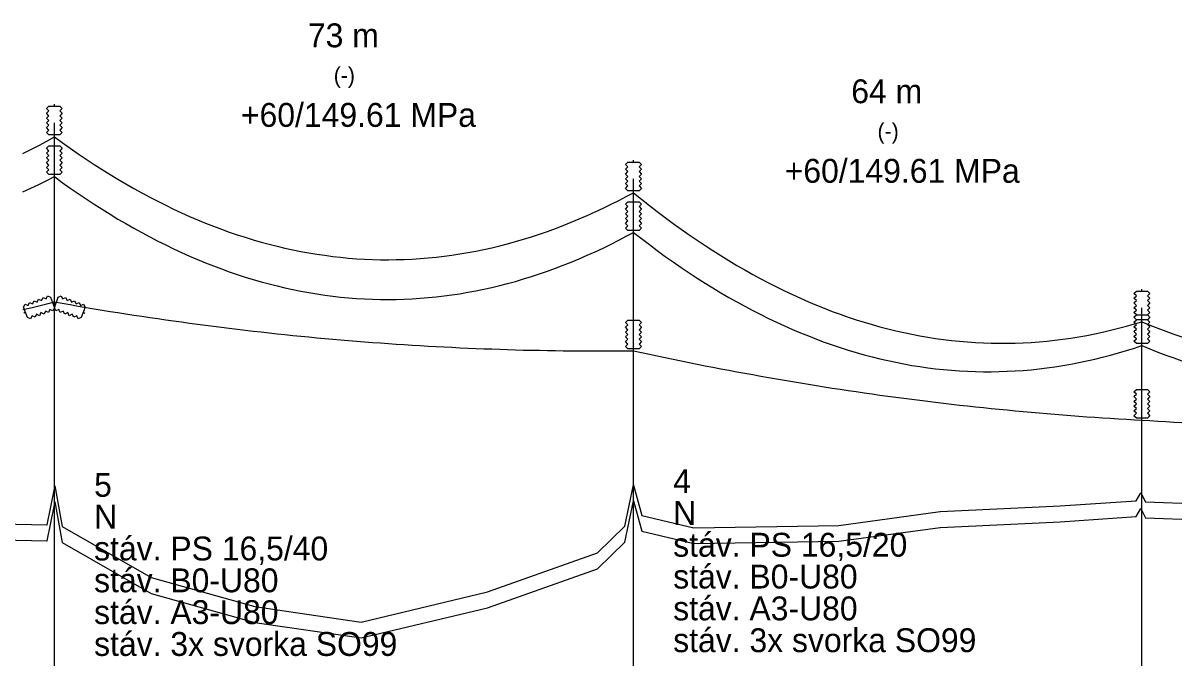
# Model space of a CAD drawing. Extents: x -21 to 625, y 813 to 990.
# Drawn here: x 314.9 to 459.7, y 910 to 989.8 of the extents above; entities that cross this region are included whole.
import ezdxf

# ---------------------------------------------------------------- set-up
doc = ezdxf.new("R2010")
doc.units = 0
for name, color, linetype in [('Vrstva 11', 7, 'Continuous'), ('Vrstva 12', 7, 'Continuous'), ('Vrstva 13', 7, 'Continuous'), ('Vrstva 14', 7, 'Continuous'), ('Vrstva 15', 7, 'Continuous'), ('Vrstva 29', 7, 'Continuous'), ('Vrstva 3', 7, 'Continuous')]:
    doc.layers.add(name, color=color, linetype=linetype)

msp = doc.modelspace()

# ---------------------------------------------------------------- linework, layer by layer
at = {"layer": 'Vrstva 11'}
for points in [[(314.9, 973.38), (315.9, 973.89), (316.9, 974.41), (317.9, 974.96), (318.86, 975.49)], [(318.86, 975.49), (319.86, 974.76), (320.86, 974.05), (321.86, 973.36), (322.86, 972.68), (323.86, 972.02), (324.86, 971.38), (325.86, 970.76), (326.86, 970.15), (327.86, 969.57), (328.86, 969), (329.86, 968.44), (330.86, 967.91), (331.86, 967.39), (332.86, 966.89), (333.86, 966.41), (334.86, 965.94), (335.86, 965.49), (336.86, 965.06), (337.86, 964.65), (338.86, 964.26), (339.86, 963.88), (340.86, 963.52), (341.86, 963.18), (342.86, 962.86), (343.86, 962.55), (344.86, 962.26), (345.86, 961.99), (346.86, 961.74), (347.86, 961.5), (348.86, 961.28), (349.86, 961.08), (350.86, 960.9), (351.86, 960.73), (352.86, 960.59), (353.86, 960.46), (354.86, 960.34), (355.86, 960.25), (356.86, 960.17), (357.86, 960.11), (358.86, 960.07), (359.86, 960.04), (360.86, 960.04), (361.86, 960.05), (362.86, 960.08), (363.86, 960.12), (364.86, 960.19), (365.86, 960.27), (366.86, 960.37), (367.86, 960.48), (368.86, 960.62), (369.86, 960.77), (370.86, 960.94), (371.86, 961.12), (372.86, 961.33), (373.86, 961.55), (374.86, 961.79), (375.86, 962.05), (376.86, 962.32), (377.86, 962.62), (378.86, 962.93), (379.86, 963.25), (380.86, 963.6), (381.86, 963.96), (382.86, 964.34), (383.86, 964.74), (384.86, 965.16), (385.86, 965.59), (386.86, 966.04), (387.86, 966.51), (388.86, 967), (389.86, 967.5), (390.86, 968.02), (391.68, 968.46)], [(314.9, 968.55), (315.9, 969.02), (316.9, 969.5), (317.9, 970), (318.86, 970.49)], [(314.9, 968.55), (315.9, 969.02), (316.9, 969.5), (317.9, 970), (318.86, 970.49)], [(318.86, 970.49), (319.86, 969.76), (320.86, 969.05), (321.86, 968.36), (322.86, 967.68), (323.86, 967.02), (324.86, 966.38), (325.86, 965.76), (326.86, 965.15), (327.86, 964.57), (328.86, 964), (329.86, 963.44), (330.86, 962.91), (331.86, 962.39), (332.86, 961.89), (333.86, 961.41), (334.86, 960.94), (335.86, 960.49), (336.86, 960.06), (337.86, 959.65), (338.86, 959.26), (339.86, 958.88), (340.86, 958.52), (341.86, 958.18), (342.86, 957.86), (343.86, 957.55), (344.86, 957.26), (345.86, 956.99), (346.86, 956.74), (347.86, 956.5), (348.86, 956.28), (349.86, 956.08), (350.86, 955.9), (351.86, 955.73), (352.86, 955.59), (353.86, 955.46), (354.86, 955.34), (355.86, 955.25), (356.86, 955.17), (357.86, 955.11), (358.86, 955.07), (359.86, 955.04), (360.86, 955.04), (361.86, 955.05), (362.86, 955.08), (363.86, 955.12), (364.86, 955.19), (365.86, 955.27), (366.86, 955.37), (367.86, 955.48), (368.86, 955.62), (369.86, 955.77), (370.86, 955.94), (371.86, 956.12), (372.86, 956.33), (373.86, 956.55), (374.86, 956.79), (375.86, 957.05), (376.86, 957.32), (377.86, 957.62), (378.86, 957.93), (379.86, 958.25), (380.86, 958.6), (381.86, 958.96), (382.86, 959.34), (383.86, 959.74), (384.86, 960.16), (385.86, 960.59), (386.86, 961.04), (387.86, 961.51), (388.86, 962), (389.86, 962.5), (390.86, 963.02), (391.68, 963.46)], [(318.86, 970.49), (319.86, 969.76), (320.86, 969.05), (321.86, 968.36), (322.86, 967.68), (323.86, 967.02), (324.86, 966.38), (325.86, 965.76), (326.86, 965.15), (327.86, 964.57), (328.86, 964), (329.86, 963.44), (330.86, 962.91), (331.86, 962.39), (332.86, 961.89), (333.86, 961.41), (334.86, 960.94), (335.86, 960.49), (336.86, 960.06), (337.86, 959.65), (338.86, 959.26), (339.86, 958.88), (340.86, 958.52), (341.86, 958.18), (342.86, 957.86), (343.86, 957.55), (344.86, 957.26), (345.86, 956.99), (346.86, 956.74), (347.86, 956.5), (348.86, 956.28), (349.86, 956.08), (350.86, 955.9), (351.86, 955.73), (352.86, 955.59), (353.86, 955.46), (354.86, 955.34), (355.86, 955.25), (356.86, 955.17), (357.86, 955.11), (358.86, 955.07), (359.86, 955.04), (360.86, 955.04), (361.86, 955.05), (362.86, 955.08), (363.86, 955.12), (364.86, 955.19), (365.86, 955.27), (366.86, 955.37), (367.86, 955.48), (368.86, 955.62), (369.86, 955.77), (370.86, 955.94), (371.86, 956.12), (372.86, 956.33), (373.86, 956.55), (374.86, 956.79), (375.86, 957.05), (376.86, 957.32), (377.86, 957.62), (378.86, 957.93), (379.86, 958.25), (380.86, 958.6), (381.86, 958.96), (382.86, 959.34), (383.86, 959.74), (384.86, 960.16), (385.86, 960.59), (386.86, 961.04), (387.86, 961.51), (388.86, 962), (389.86, 962.5), (390.86, 963.02), (391.68, 963.46)], [(391.68, 968.46), (392.68, 967.66), (393.68, 966.87), (394.68, 966.09), (395.68, 965.34), (396.68, 964.6), (397.68, 963.88), (398.68, 963.18), (399.68, 962.49), (400.68, 961.83), (401.68, 961.18), (402.68, 960.55), (403.68, 959.93), (404.68, 959.33), (405.68, 958.76), (406.68, 958.19), (407.68, 957.65), (408.68, 957.12), (409.68, 956.62), (410.68, 956.13), (411.68, 955.65), (412.68, 955.2), (413.68, 954.76), (414.68, 954.34), (415.68, 953.94), (416.68, 953.55), (417.68, 953.18), (418.68, 952.83), (419.68, 952.5), (420.68, 952.19), (421.68, 951.89), (422.68, 951.61), (423.68, 951.35), (424.68, 951.1), (425.68, 950.88), (426.68, 950.67), (427.68, 950.48), (428.68, 950.3), (429.68, 950.15), (430.68, 950.01), (431.68, 949.89), (432.68, 949.78), (433.68, 949.7), (434.68, 949.63), (435.68, 949.58), (436.68, 949.55), (437.68, 949.53), (438.68, 949.54), (439.68, 949.56), (440.68, 949.59), (441.68, 949.65), (442.68, 949.72), (443.68, 949.81), (444.68, 949.92), (445.68, 950.05), (446.68, 950.19), (447.68, 950.35), (448.68, 950.53), (449.68, 950.72), (450.68, 950.94), (451.68, 951.17), (452.68, 951.42), (453.68, 951.69), (454.68, 951.97), (455.62, 952.25)], [(391.68, 963.46), (392.68, 962.69), (393.68, 961.93), (394.68, 961.19), (395.68, 960.46), (396.68, 959.76), (397.68, 959.07), (398.68, 958.4), (399.68, 957.74), (400.68, 957.11), (401.68, 956.49), (402.68, 955.89), (403.68, 955.31), (404.68, 954.74), (405.68, 954.19), (406.68, 953.66), (407.68, 953.15), (408.68, 952.66), (409.68, 952.18), (410.68, 951.72), (411.68, 951.28), (412.68, 950.85), (413.68, 950.45), (414.68, 950.06), (415.68, 949.69), (416.68, 949.33), (417.68, 949), (418.68, 948.68), (419.68, 948.38), (420.68, 948.09), (421.68, 947.83), (422.68, 947.58), (423.68, 947.35), (424.68, 947.14), (425.68, 946.94), (426.68, 946.76), (427.68, 946.6), (428.68, 946.46), (429.68, 946.34), (430.68, 946.23), (431.68, 946.14), (432.68, 946.07), (433.68, 946.01), (434.68, 945.98), (435.68, 945.96), (436.68, 945.96), (437.68, 945.97), (438.68, 946.01), (439.68, 946.06), (440.68, 946.13), (441.68, 946.21), (442.68, 946.32), (443.68, 946.44), (444.68, 946.58), (445.68, 946.73), (446.68, 946.91), (447.68, 947.1), (448.68, 947.31), (449.68, 947.54), (450.68, 947.78), (451.68, 948.05), (452.68, 948.33), (453.68, 948.63), (454.68, 948.94), (455.62, 949.25)], [(391.68, 963.46), (392.68, 962.69), (393.68, 961.93), (394.68, 961.19), (395.68, 960.46), (396.68, 959.76), (397.68, 959.07), (398.68, 958.4), (399.68, 957.74), (400.68, 957.11), (401.68, 956.49), (402.68, 955.89), (403.68, 955.31), (404.68, 954.74), (405.68, 954.19), (406.68, 953.66), (407.68, 953.15), (408.68, 952.66), (409.68, 952.18), (410.68, 951.72), (411.68, 951.28), (412.68, 950.85), (413.68, 950.45), (414.68, 950.06), (415.68, 949.69), (416.68, 949.33), (417.68, 949), (418.68, 948.68), (419.68, 948.38), (420.68, 948.09), (421.68, 947.83), (422.68, 947.58), (423.68, 947.35), (424.68, 947.14), (425.68, 946.94), (426.68, 946.76), (427.68, 946.6), (428.68, 946.46), (429.68, 946.34), (430.68, 946.23), (431.68, 946.14), (432.68, 946.07), (433.68, 946.01), (434.68, 945.98), (435.68, 945.96), (436.68, 945.96), (437.68, 945.97), (438.68, 946.01), (439.68, 946.06), (440.68, 946.13), (441.68, 946.21), (442.68, 946.32), (443.68, 946.44), (444.68, 946.58), (445.68, 946.73), (446.68, 946.91), (447.68, 947.1), (448.68, 947.31), (449.68, 947.54), (450.68, 947.78), (451.68, 948.05), (452.68, 948.33), (453.68, 948.63), (454.68, 948.94), (455.62, 949.25)], [(314.9, 953.77), (315.9, 954.01), (316.9, 954.26), (317.9, 954.5), (318.86, 954.74)], [(318.86, 954.74), (319.86, 954.57), (320.86, 954.39), (321.86, 954.22), (322.86, 954.05), (323.86, 953.88), (324.86, 953.71), (325.86, 953.55), (326.86, 953.39), (327.86, 953.23), (328.86, 953.08), (329.86, 952.93), (330.86, 952.78), (331.86, 952.63), (332.86, 952.49), (333.86, 952.34), (334.86, 952.21), (335.86, 952.07), (336.86, 951.94), (337.86, 951.8), (338.86, 951.68), (339.86, 951.55), (340.86, 951.43), (341.86, 951.31), (342.86, 951.19), (343.86, 951.07), (344.86, 950.96), (345.86, 950.85), (346.86, 950.74), (347.86, 950.64), (348.86, 950.53), (349.86, 950.43), (350.86, 950.34), (351.86, 950.24), (352.86, 950.15), (353.86, 950.06), (354.86, 949.97), (355.86, 949.89), (356.86, 949.81), (357.86, 949.73), (358.86, 949.65), (359.86, 949.58), (360.86, 949.51), (361.86, 949.44), (362.86, 949.37), (363.86, 949.31), (364.86, 949.25), (365.86, 949.19), (366.86, 949.13), (367.86, 949.08), (368.86, 949.03), (369.86, 948.98), (370.86, 948.94), (371.86, 948.89), (372.86, 948.85), (373.86, 948.82), (374.86, 948.78), (375.86, 948.75), (376.86, 948.72), (377.86, 948.69), (378.86, 948.67), (379.86, 948.65), (380.86, 948.63), (381.86, 948.61), (382.86, 948.6), (383.86, 948.59), (384.86, 948.58), (385.86, 948.57), (386.86, 948.57), (387.86, 948.57), (388.86, 948.57), (389.86, 948.57), (390.86, 948.58), (391.68, 948.59)], [(455.62, 952.25), (456.62, 951.83), (457.62, 951.43), (458.62, 951.05), (459.62, 950.69), (460.62, 950.34)], [(391.68, 948.59), (392.68, 948.37), (393.68, 948.15), (394.68, 947.94), (395.68, 947.73), (396.68, 947.52), (397.68, 947.32), (398.68, 947.11), (399.68, 946.91), (400.68, 946.72), (401.68, 946.52), (402.68, 946.33), (403.68, 946.14), (404.68, 945.95), (405.68, 945.77), (406.68, 945.59), (407.68, 945.41), (408.68, 945.23), (409.68, 945.06), (410.68, 944.88), (411.68, 944.72), (412.68, 944.55), (413.68, 944.39), (414.68, 944.22), (415.68, 944.07), (416.68, 943.91), (417.68, 943.76), (418.68, 943.61), (419.68, 943.46), (420.68, 943.31), (421.68, 943.17), (422.68, 943.03), (423.68, 942.89), (424.68, 942.76), (425.68, 942.63), (426.68, 942.5), (427.68, 942.37), (428.68, 942.25), (429.68, 942.12), (430.68, 942), (431.68, 941.89), (432.68, 941.77), (433.68, 941.66), (434.68, 941.55), (435.68, 941.45), (436.68, 941.34), (437.68, 941.24), (438.68, 941.15), (439.68, 941.05), (440.68, 940.96), (441.68, 940.87), (442.68, 940.78), (443.68, 940.69), (444.68, 940.61), (445.68, 940.53), (446.68, 940.45), (447.68, 940.38), (448.68, 940.31), (449.68, 940.24), (450.68, 940.17), (451.68, 940.11), (452.68, 940.04), (453.68, 939.98), (454.68, 939.93), (455.62, 939.88)], [(455.62, 949.25), (456.62, 948.83), (457.62, 948.43), (458.62, 948.05), (459.62, 947.69), (460.62, 947.34)], [(455.62, 949.25), (456.62, 948.83), (457.62, 948.43), (458.62, 948.05), (459.62, 947.69), (460.62, 947.34)], [(455.62, 939.88), (456.62, 939.81), (457.62, 939.75), (458.62, 939.7), (459.62, 939.64), (460.62, 939.59)]]:
    msp.add_lwpolyline(points, dxfattribs=at)
at = {"layer": 'Vrstva 14'}
for p, q in [((318.86, 901.24), (318.86, 977.24)), ((391.68, 901.71), (391.68, 970.21)), ((455.62, 900.5), (455.62, 954))]:
    msp.add_line(p, q, dxfattribs=at)
at = {"layer": 'Vrstva 29'}
for points in [[(319.56, 975.74), (318.16, 975.74), (317.86, 976.04), (318.16, 976.34), (317.86, 976.64), (318.16, 976.94), (317.86, 977.24), (318.16, 977.54), (317.86, 977.84), (318.16, 978.14), (317.86, 978.44), (318.16, 978.74), (317.86, 979.04), (318.16, 979.34), (319.56, 979.34), (319.86, 979.04), (319.56, 978.74), (319.86, 978.44), (319.56, 978.14), (319.86, 977.84), (319.56, 977.54), (319.86, 977.24), (319.56, 976.94), (319.86, 976.64), (319.56, 976.34), (319.86, 976.04)], [(319.56, 970.74), (318.16, 970.74), (317.86, 971.04), (318.16, 971.34), (317.86, 971.64), (318.16, 971.94), (317.86, 972.24), (318.16, 972.54), (317.86, 972.84), (318.16, 973.14), (317.86, 973.44), (318.16, 973.74), (317.86, 974.04), (318.16, 974.34), (319.56, 974.34), (319.86, 974.04), (319.56, 973.74), (319.86, 973.44), (319.56, 973.14), (319.86, 972.84), (319.56, 972.54), (319.86, 972.24), (319.56, 971.94), (319.86, 971.64), (319.56, 971.34), (319.86, 971.04)], [(319.56, 970.74), (318.16, 970.74), (317.86, 971.04), (318.16, 971.34), (317.86, 971.64), (318.16, 971.94), (317.86, 972.24), (318.16, 972.54), (317.86, 972.84), (318.16, 973.14), (317.86, 973.44), (318.16, 973.74), (317.86, 974.04), (318.16, 974.34), (319.56, 974.34), (319.86, 974.04), (319.56, 973.74), (319.86, 973.44), (319.56, 973.14), (319.86, 972.84), (319.56, 972.54), (319.86, 972.24), (319.56, 971.94), (319.86, 971.64), (319.56, 971.34), (319.86, 971.04)], [(392.38, 968.71), (390.98, 968.71), (390.68, 969.01), (390.98, 969.31), (390.68, 969.61), (390.98, 969.91), (390.68, 970.21), (390.98, 970.51), (390.68, 970.81), (390.98, 971.11), (390.68, 971.41), (390.98, 971.71), (390.68, 972.01), (390.98, 972.31), (392.38, 972.31), (392.68, 972.01), (392.38, 971.71), (392.68, 971.41), (392.38, 971.11), (392.68, 970.81), (392.38, 970.51), (392.68, 970.21), (392.38, 969.91), (392.68, 969.61), (392.38, 969.31), (392.68, 969.01)], [(392.38, 963.71), (390.98, 963.71), (390.68, 964.01), (390.98, 964.31), (390.68, 964.61), (390.98, 964.91), (390.68, 965.21), (390.98, 965.51), (390.68, 965.81), (390.98, 966.11), (390.68, 966.41), (390.98, 966.71), (390.68, 967.01), (390.98, 967.31), (392.38, 967.31), (392.68, 967.01), (392.38, 966.71), (392.68, 966.41), (392.38, 966.11), (392.68, 965.81), (392.38, 965.51), (392.68, 965.21), (392.38, 964.91), (392.68, 964.61), (392.38, 964.31), (392.68, 964.01)], [(392.38, 963.71), (390.98, 963.71), (390.68, 964.01), (390.98, 964.31), (390.68, 964.61), (390.98, 964.91), (390.68, 965.21), (390.98, 965.51), (390.68, 965.81), (390.98, 966.11), (390.68, 966.41), (390.98, 966.71), (390.68, 967.01), (390.98, 967.31), (392.38, 967.31), (392.68, 967.01), (392.38, 966.71), (392.68, 966.41), (392.38, 966.11), (392.68, 965.81), (392.38, 965.51), (392.68, 965.21), (392.38, 964.91), (392.68, 964.61), (392.38, 964.31), (392.68, 964.01)], [(318.39, 955.32), (318.87, 954), (318.69, 953.62), (318.3, 953.8), (318.12, 953.41), (317.74, 953.59), (317.56, 953.21), (317.17, 953.39), (317, 953), (316.61, 953.18), (316.43, 952.8), (316.05, 952.97), (315.87, 952.59), (315.48, 952.77), (315, 954.08), (315.18, 954.47), (315.57, 954.29), (315.75, 954.67), (316.13, 954.5), (316.31, 954.88), (316.7, 954.7), (316.87, 955.09), (317.26, 954.91), (317.44, 955.29), (317.82, 955.11), (318, 955.5)], [(318.86, 954), (319.34, 955.32), (319.72, 955.5), (319.9, 955.11), (320.28, 955.29), (320.46, 954.91), (320.85, 955.09), (321.03, 954.7), (321.41, 954.88), (321.59, 954.5), (321.98, 954.67), (322.15, 954.29), (322.54, 954.47), (322.72, 954.08), (322.24, 952.77), (321.86, 952.59), (321.68, 952.97), (321.29, 952.8), (321.11, 953.18), (320.73, 953), (320.55, 953.39), (320.16, 953.21), (319.98, 953.59), (319.6, 953.41), (319.42, 953.8), (319.04, 953.62)], [(456.32, 952.5), (454.92, 952.5), (454.62, 952.8), (454.92, 953.1), (454.62, 953.4), (454.92, 953.7), (454.62, 954), (454.92, 954.3), (454.62, 954.6), (454.92, 954.9), (454.62, 955.2), (454.92, 955.5), (454.62, 955.8), (454.92, 956.1), (456.32, 956.1), (456.62, 955.8), (456.32, 955.5), (456.62, 955.2), (456.32, 954.9), (456.62, 954.6), (456.32, 954.3), (456.62, 954), (456.32, 953.7), (456.62, 953.4), (456.32, 953.1), (456.62, 952.8)], [(392.38, 948.84), (390.98, 948.84), (390.68, 949.14), (390.98, 949.44), (390.68, 949.74), (390.98, 950.04), (390.68, 950.34), (390.98, 950.64), (390.68, 950.94), (390.98, 951.24), (390.68, 951.54), (390.98, 951.84), (390.68, 952.14), (390.98, 952.44), (392.38, 952.44), (392.68, 952.14), (392.38, 951.84), (392.68, 951.54), (392.38, 951.24), (392.68, 950.94), (392.38, 950.64), (392.68, 950.34), (392.38, 950.04), (392.68, 949.74), (392.38, 949.44), (392.68, 949.14)], [(392.38, 948.84), (390.98, 948.84), (390.68, 949.14), (390.98, 949.44), (390.68, 949.74), (390.98, 950.04), (390.68, 950.34), (390.98, 950.64), (390.68, 950.94), (390.98, 951.24), (390.68, 951.54), (390.98, 951.84), (390.68, 952.14), (390.98, 952.44), (392.38, 952.44), (392.68, 952.14), (392.38, 951.84), (392.68, 951.54), (392.38, 951.24), (392.68, 950.94), (392.38, 950.64), (392.68, 950.34), (392.38, 950.04), (392.68, 949.74), (392.38, 949.44), (392.68, 949.14)], [(456.32, 949.5), (454.92, 949.5), (454.62, 949.8), (454.92, 950.1), (454.62, 950.4), (454.92, 950.7), (454.62, 951), (454.92, 951.3), (454.62, 951.6), (454.92, 951.9), (454.62, 952.2), (454.92, 952.5), (454.62, 952.8), (454.92, 953.1), (456.32, 953.1), (456.62, 952.8), (456.32, 952.5), (456.62, 952.2), (456.32, 951.9), (456.62, 951.6), (456.32, 951.3), (456.62, 951), (456.32, 950.7), (456.62, 950.4), (456.32, 950.1), (456.62, 949.8)], [(456.32, 949.5), (454.92, 949.5), (454.62, 949.8), (454.92, 950.1), (454.62, 950.4), (454.92, 950.7), (454.62, 951), (454.92, 951.3), (454.62, 951.6), (454.92, 951.9), (454.62, 952.2), (454.92, 952.5), (454.62, 952.8), (454.92, 953.1), (456.32, 953.1), (456.62, 952.8), (456.32, 952.5), (456.62, 952.2), (456.32, 951.9), (456.62, 951.6), (456.32, 951.3), (456.62, 951), (456.32, 950.7), (456.62, 950.4), (456.32, 950.1), (456.62, 949.8)], [(456.32, 940.13), (454.92, 940.13), (454.62, 940.43), (454.92, 940.73), (454.62, 941.03), (454.92, 941.33), (454.62, 941.63), (454.92, 941.93), (454.62, 942.23), (454.92, 942.53), (454.62, 942.83), (454.92, 943.13), (454.62, 943.43), (454.92, 943.73), (456.32, 943.73), (456.62, 943.43), (456.32, 943.13), (456.62, 942.83), (456.32, 942.53), (456.62, 942.23), (456.32, 941.93), (456.62, 941.63), (456.32, 941.33), (456.62, 941.03), (456.32, 940.73), (456.62, 940.43)]]:
    msp.add_lwpolyline(points, close=True, dxfattribs=at)
for points in [[(318.86, 979.34), (318.86, 979.59)], [(318.86, 975.49), (318.86, 975.74)], [(318.86, 974.34), (318.86, 974.59)], [(318.86, 974.34), (318.86, 974.59)], [(391.68, 972.31), (391.68, 972.56)], [(318.86, 970.49), (318.86, 970.74)], [(318.86, 970.49), (318.86, 970.74)], [(391.68, 968.46), (391.68, 968.71)], [(391.68, 967.31), (391.68, 967.56)], [(391.68, 967.31), (391.68, 967.56)], [(391.68, 963.46), (391.68, 963.71)], [(391.68, 963.46), (391.68, 963.71)], [(455.62, 956.1), (455.62, 956.35)], [(318.86, 954.74), (318.63, 954.66)], [(318.86, 954.74), (319.1, 954.66)], [(315.24, 953.43), (315.01, 953.34)], [(322.48, 953.43), (322.71, 953.34)], [(391.68, 952.44), (391.68, 952.69)], [(391.68, 952.44), (391.68, 952.69)], [(455.62, 953.1), (455.62, 953.35)], [(455.62, 953.1), (455.62, 953.35)], [(455.62, 952.25), (455.62, 952.5)], [(455.62, 949.25), (455.62, 949.5)], [(455.62, 949.25), (455.62, 949.5)], [(391.68, 948.59), (391.68, 948.84)], [(391.68, 948.59), (391.68, 948.84)], [(455.62, 943.73), (455.62, 943.98)], [(455.62, 939.88), (455.62, 940.13)]]:
    msp.add_lwpolyline(points, dxfattribs=at)
at = {"layer": 'Vrstva 3'}
for p, q in [((317.94, 926.7), (318.86, 931.24)), ((318.86, 931.24), (318.93, 931.6)), ((318.93, 931.6), (319.85, 926.5)), ((390.6, 926.55), (391.67, 931.75)), ((391.67, 931.75), (391.68, 931.72)), ((391.68, 931.72), (392.74, 927.9)), ((454.9, 929.75), (455.49, 930.75)), ((455.49, 930.75), (455.62, 930.5)), ((317.94, 924.7), (318.86, 929.24)), ((317.94, 924.7), (318.86, 929.24)), ((317.94, 924.7), (318.86, 929.24)), ((318.86, 929.24), (318.93, 929.6)), ((318.86, 929.24), (318.93, 929.6)), ((318.86, 929.24), (318.93, 929.6)), ((318.93, 929.6), (319.85, 924.5)), ((318.93, 929.6), (319.85, 924.5)), ((318.93, 929.6), (319.85, 924.5)), ((390.6, 924.55), (391.67, 929.75)), ((390.6, 924.55), (391.67, 929.75)), ((390.6, 924.55), (391.67, 929.75)), ((391.67, 929.75), (391.68, 929.72)), ((391.67, 929.75), (391.68, 929.72)), ((391.67, 929.75), (391.68, 929.72)), ((391.68, 929.72), (392.74, 925.9)), ((391.68, 929.72), (392.74, 925.9)), ((391.68, 929.72), (392.74, 925.9)), ((445.35, 929.1), (454.9, 929.75)), ((455.62, 930.5), (456.07, 929.6)), ((456.07, 929.6), (467.07, 929.2)), ((392.74, 927.9), (399.26, 926.35)), ((417.52, 926.65), (430.26, 928.4)), ((430.26, 928.4), (430.31, 928.4)), ((430.31, 928.4), (445.35, 929.1)), ((445.35, 927.1), (454.9, 927.75)), ((445.35, 927.1), (454.9, 927.75)), ((445.35, 927.1), (454.9, 927.75)), ((454.9, 927.75), (455.49, 928.75)), ((454.9, 927.75), (455.49, 928.75)), ((454.9, 927.75), (455.49, 928.75)), ((455.49, 928.75), (455.62, 928.5)), ((455.49, 928.75), (455.62, 928.5)), ((455.49, 928.75), (455.62, 928.5)), ((455.62, 928.5), (456.07, 927.6)), ((455.62, 928.5), (456.07, 927.6)), ((455.62, 928.5), (456.07, 927.6)), ((312.13, 926.85), (317.9, 926.7)), ((317.9, 926.7), (317.94, 926.7)), ((319.85, 926.5), (331.03, 920.1)), ((387.18, 923.2), (390.6, 926.55)), ((399.26, 926.35), (417.52, 926.65)), ((417.52, 924.65), (430.26, 926.4)), ((417.52, 924.65), (430.26, 926.4)), ((417.52, 924.65), (430.26, 926.4)), ((430.26, 926.4), (430.31, 926.4)), ((430.26, 926.4), (430.31, 926.4)), ((430.26, 926.4), (430.31, 926.4)), ((430.31, 926.4), (445.35, 927.1)), ((430.31, 926.4), (445.35, 927.1)), ((430.31, 926.4), (445.35, 927.1)), ((456.07, 927.6), (467.07, 927.2)), ((456.07, 927.6), (467.07, 927.2)), ((456.07, 927.6), (467.07, 927.2)), ((312.13, 924.85), (317.9, 924.7)), ((312.13, 924.85), (317.9, 924.7)), ((312.13, 924.85), (317.9, 924.7)), ((392.74, 925.9), (399.26, 924.35)), ((392.74, 925.9), (399.26, 924.35)), ((392.74, 925.9), (399.26, 924.35)), ((317.9, 924.7), (317.94, 924.7)), ((317.9, 924.7), (317.94, 924.7)), ((317.9, 924.7), (317.94, 924.7)), ((319.85, 924.5), (331.03, 918.1)), ((319.85, 924.5), (331.03, 918.1)), ((319.85, 924.5), (331.03, 918.1)), ((387.18, 921.2), (390.6, 924.55)), ((387.18, 921.2), (390.6, 924.55)), ((387.18, 921.2), (390.6, 924.55)), ((399.26, 924.35), (417.52, 924.65)), ((399.26, 924.35), (417.52, 924.65)), ((399.26, 924.35), (417.52, 924.65)), ((373.33, 918.3), (387.18, 923.2)), ((373.33, 916.3), (387.18, 921.2)), ((373.33, 916.3), (387.18, 921.2)), ((373.33, 916.3), (387.18, 921.2)), ((331.03, 920.1), (344.07, 916.45)), ((331.03, 918.1), (344.07, 914.45)), ((331.03, 918.1), (344.07, 914.45)), ((331.03, 918.1), (344.07, 914.45)), ((357.43, 914.5), (373.33, 918.3)), ((344.07, 916.45), (357.43, 914.5)), ((357.43, 912.5), (373.33, 916.3)), ((357.43, 912.5), (373.33, 916.3)), ((357.43, 912.5), (373.33, 916.3)), ((344.07, 914.45), (357.43, 912.5)), ((344.07, 914.45), (357.43, 912.5)), ((344.07, 914.45), (357.43, 912.5))]:
    msp.add_line(p, q, dxfattribs=at)

# ---------------------------------------------------------------- texts
at = {"layer": 'Vrstva 12'}
for p in [(342.32, 976.74), (410.7, 969.71)]:
    msp.add_text('+60/149.61 MPa', height=3, dxfattribs=at).set_placement(p)
at = {"layer": 'Vrstva 13'}
for s, height, p in [('73 m', 3, (350.74, 986.74)), ('(-)', 2, (353.99, 982.24)), ('64 m', 3, (419.07, 979.71)), ('(-)', 2, (422.37, 975.21))]:
    msp.add_text(s, height=height, dxfattribs=at).set_placement(p)
at = {"layer": 'Vrstva 15'}
for s, p in [('4', (396.68, 930.71)), ('5', (323.86, 930.24)), ('N', (323.86, 926.24)), ('N', (396.68, 926.71)), ('stáv. PS 16,5/40', (323.86, 922.24)), ('stáv. PS 16,5/20', (396.68, 922.71)), ('stáv. B0-U80', (323.86, 918.24)), ('stáv. B0-U80', (396.68, 918.71)), ('stáv. A3-U80', (396.68, 914.71)), ('stáv. A3-U80', (323.86, 914.24)), ('stáv. 3x svorka SO99', (323.86, 910.24)), ('stáv. 3x svorka SO99', (396.68, 910.71))]:
    msp.add_text(s, height=3, dxfattribs=at).set_placement(p)

doc.saveas('drawing.dxf')
